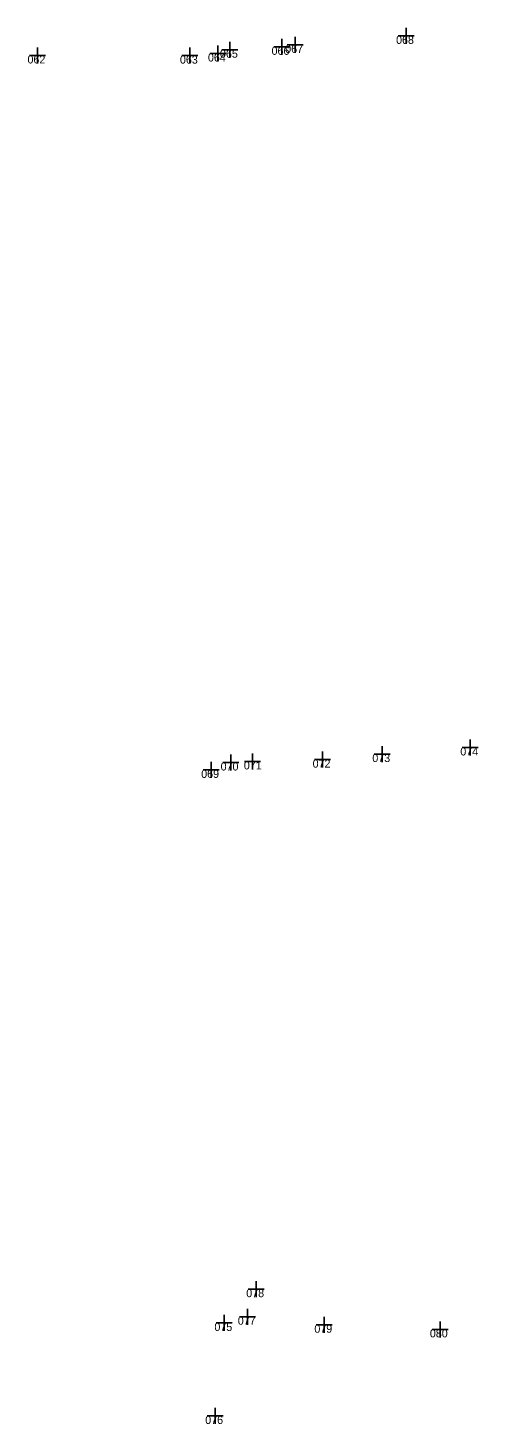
# Model space of a CAD drawing. Extents: x -706655 to -706193, y -1036183 to -1035040.
# Drawn here: x -706419.9 to -706391.8, y -1035433.7 to -1035346.5 of the extents above; entities that cross this region are included whole.
import ezdxf

# ---------------------------------------------------------------- set-up
doc = ezdxf.new("R2010")
doc.units = 0
doc.layers.add('čísla bodu', color=7, linetype='Continuous')

msp = doc.modelspace()

# ---------------------------------------------------------------- linework, layer by layer
at = {"layer": 'čísla bodu'}
for p, q in [((-706404.04, -1035348.13), (-706404.04, -1035347.13)), ((-706403.2, -1035348.01), (-706403.2, -1035347.01)), ((-706396.77, -1035346.95), (-706395.77, -1035346.95)), ((-706396.27, -1035347.45), (-706396.27, -1035346.45)), ((-706396.27, -1035346.95), (-706396.27, -1035346.95)), ((-706419.31, -1035348.67), (-706419.31, -1035347.67)), ((-706409.78, -1035348.68), (-706409.78, -1035347.68)), ((-706408.53, -1035348.05), (-706407.53, -1035348.05)), ((-706408.03, -1035348.55), (-706408.03, -1035347.55)), ((-706408.03, -1035348.05), (-706408.03, -1035348.05)), ((-706407.78, -1035347.81), (-706406.78, -1035347.81)), ((-706407.28, -1035348.31), (-706407.28, -1035347.31)), ((-706407.28, -1035347.81), (-706407.28, -1035347.81)), ((-706404.54, -1035347.63), (-706403.54, -1035347.63)), ((-706404.04, -1035347.63), (-706404.04, -1035347.63)), ((-706403.7, -1035347.51), (-706402.7, -1035347.51)), ((-706403.2, -1035347.51), (-706403.2, -1035347.51)), ((-706419.81, -1035348.17), (-706418.81, -1035348.17)), ((-706419.31, -1035348.17), (-706419.31, -1035348.17)), ((-706410.28, -1035348.18), (-706409.28, -1035348.18)), ((-706409.78, -1035348.18), (-706409.78, -1035348.18)), ((-706401.5, -1035392.66), (-706401.5, -1035391.66)), ((-706397.77, -1035392.31), (-706397.77, -1035391.31)), ((-706392.77, -1035391.4), (-706391.77, -1035391.4)), ((-706392.27, -1035391.9), (-706392.27, -1035390.9)), ((-706392.27, -1035391.4), (-706392.27, -1035391.4)), ((-706408.45, -1035393.3), (-706408.45, -1035392.3)), ((-706407.73, -1035392.34), (-706406.73, -1035392.34)), ((-706407.23, -1035392.84), (-706407.23, -1035391.84)), ((-706407.23, -1035392.34), (-706407.23, -1035392.34)), ((-706406.37, -1035392.27), (-706405.37, -1035392.27)), ((-706405.87, -1035392.77), (-706405.87, -1035391.77)), ((-706405.87, -1035392.27), (-706405.87, -1035392.27)), ((-706402, -1035392.16), (-706401, -1035392.16)), ((-706401.5, -1035392.16), (-706401.5, -1035392.16)), ((-706398.27, -1035391.81), (-706397.27, -1035391.81)), ((-706397.77, -1035391.81), (-706397.77, -1035391.81)), ((-706408.95, -1035392.8), (-706407.95, -1035392.8)), ((-706408.45, -1035392.8), (-706408.45, -1035392.8)), ((-706405.65, -1035425.74), (-706405.65, -1035424.74)), ((-706406.15, -1035425.24), (-706405.15, -1035425.24)), ((-706405.65, -1035425.24), (-706405.65, -1035425.24)), ((-706406.18, -1035427.46), (-706406.18, -1035426.46)), ((-706408.14, -1035427.35), (-706407.14, -1035427.35)), ((-706407.64, -1035427.85), (-706407.64, -1035426.85)), ((-706407.64, -1035427.35), (-706407.64, -1035427.35)), ((-706406.68, -1035426.96), (-706405.68, -1035426.96)), ((-706406.18, -1035426.96), (-706406.18, -1035426.96)), ((-706401.39, -1035427.96), (-706401.39, -1035426.96)), ((-706394.15, -1035428.25), (-706394.15, -1035427.25)), ((-706401.89, -1035427.46), (-706400.89, -1035427.46)), ((-706401.39, -1035427.46), (-706401.39, -1035427.46)), ((-706394.65, -1035427.75), (-706393.65, -1035427.75)), ((-706394.15, -1035427.75), (-706394.15, -1035427.75)), ((-706408.7, -1035433.16), (-706407.7, -1035433.16)), ((-706408.2, -1035433.66), (-706408.2, -1035432.66)), ((-706408.2, -1035433.16), (-706408.2, -1035433.16))]:
    msp.add_line(p, q, dxfattribs=at)

# ---------------------------------------------------------------- texts
for s, p in [('068', (-706396.896, -1035347.45)), ('064', (-706408.656, -1035348.55)), ('065', (-706407.906, -1035348.31)), ('066', (-706404.68, -1035348.13)), ('067', (-706403.826, -1035348.01)), ('062', (-706419.936, -1035348.67)), ('063', (-706410.406, -1035348.68)), ('074', (-706392.882, -1035391.9)), ('070', (-706407.864, -1035392.84)), ('071', (-706406.412, -1035392.77)), ('072', (-706402.112, -1035392.66)), ('073', (-706398.382, -1035392.31)), ('069', (-706409.078, -1035393.3)), ('078', (-706406.262, -1035425.74)), ('075', (-706408.252, -1035427.85)), ('077', (-706406.792, -1035427.46)), ('079', (-706402.004, -1035427.96)), ('080', (-706394.784, -1035428.25)), ('076', (-706408.826, -1035433.66))]:
    msp.add_text(s, height=0.5, dxfattribs=at).set_placement(p)

doc.saveas('drawing.dxf')
